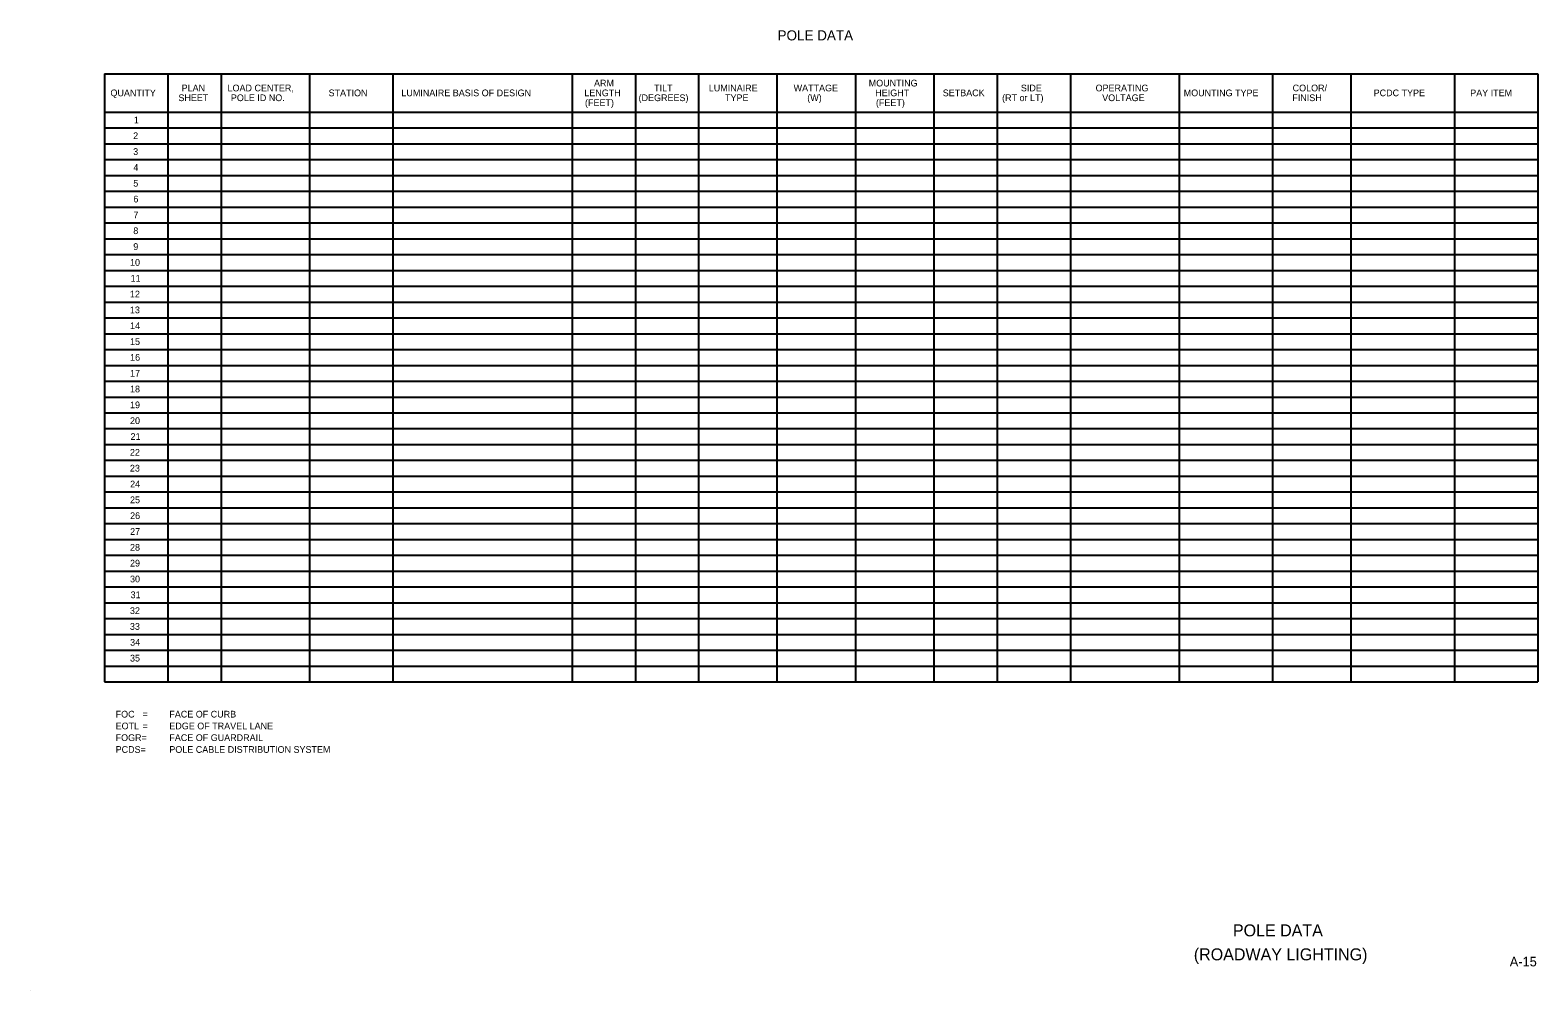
# Model space of a CAD drawing. Extents: x -830028.7 to -830013, y 1290283.4 to 1290293.4.
import ezdxf

# ---------------------------------------------------------------- set-up
doc = ezdxf.new("R2010")
doc.units = 0
for name, color, linetype in [('AdhocPoint_dp', 7, 'Continuous'), ('SumBoxBorder_dp', 7, 'Continuous'), ('SumBoxLines_dp', 7, 'Continuous'), ('SumBoxLinesMin_dp', 7, 'Continuous'), ('TextLabel', 7, 'Continuous'), ('TextMisc', 7, 'Continuous'), ('TextShtNo', 7, 'Continuous')]:
    doc.layers.add(name, color=color, linetype=linetype)

msp = doc.modelspace()

# ---------------------------------------------------------------- linework, layer by layer
at = {"layer": 'AdhocPoint_dp'}
msp.add_line((-830028.694, 1290283.415), (-830028.694, 1290283.415), dxfattribs=at)
at = {"layer": 'SumBoxBorder_dp'}
for p, q in [((-830027.917, 1290292.975), (-830012.97, 1290292.975)), ((-830027.917, 1290292.975), (-830012.97, 1290292.975)), ((-830027.917, 1290292.975), (-830027.917, 1290286.635)), ((-830016.712, 1290292.975), (-830016.712, 1290292.575)), ((-830015.737, 1290292.975), (-830015.737, 1290292.575)), ((-830014.92, 1290292.975), (-830014.92, 1290292.575)), ((-830013.84, 1290292.975), (-830013.84, 1290292.575)), ((-830012.97, 1290292.975), (-830012.97, 1290286.635)), ((-830027.917, 1290292.575), (-830012.97, 1290292.575)), ((-830027.917, 1290292.575), (-830012.97, 1290292.575)), ((-830027.917, 1290286.635), (-830012.97, 1290286.635))]:
    msp.add_line(p, q, dxfattribs=at)
at = {"layer": 'SumBoxLines_dp'}
for p, q in [((-830027.257, 1290292.975), (-830027.257, 1290286.635)), ((-830027.257, 1290292.975), (-830027.257, 1290286.635)), ((-830026.702, 1290292.975), (-830026.702, 1290286.635)), ((-830026.702, 1290292.975), (-830026.702, 1290286.635)), ((-830025.78, 1290292.975), (-830025.78, 1290286.635)), ((-830025.78, 1290292.975), (-830025.78, 1290286.635)), ((-830024.91, 1290292.975), (-830024.91, 1290286.635)), ((-830024.91, 1290292.975), (-830024.91, 1290286.635)), ((-830023.042, 1290292.975), (-830023.042, 1290286.635)), ((-830023.042, 1290292.975), (-830023.042, 1290286.635)), ((-830022.382, 1290292.975), (-830022.382, 1290286.635)), ((-830022.382, 1290292.975), (-830022.382, 1290286.635)), ((-830021.722, 1290292.975), (-830021.722, 1290286.635)), ((-830021.722, 1290292.975), (-830021.722, 1290286.635)), ((-830020.905, 1290292.975), (-830020.905, 1290286.635)), ((-830020.905, 1290292.975), (-830020.905, 1290286.635)), ((-830020.087, 1290292.975), (-830020.087, 1290286.635)), ((-830020.087, 1290292.975), (-830020.087, 1290286.635)), ((-830019.27, 1290292.975), (-830019.27, 1290286.635)), ((-830019.27, 1290292.975), (-830019.27, 1290286.635)), ((-830018.61, 1290292.975), (-830018.61, 1290286.635)), ((-830018.61, 1290292.975), (-830018.61, 1290286.635)), ((-830017.845, 1290292.975), (-830017.845, 1290286.635)), ((-830016.712, 1290292.975), (-830016.712, 1290286.635)), ((-830015.737, 1290292.975), (-830015.737, 1290286.635)), ((-830014.92, 1290292.975), (-830014.92, 1290286.635)), ((-830013.84, 1290292.975), (-830013.84, 1290286.635))]:
    msp.add_line(p, q, dxfattribs=at)
at = {"layer": 'SumBoxLinesMin_dp'}
for p, q in [((-830027.917, 1290292.41), (-830012.97, 1290292.41)), ((-830027.917, 1290292.41), (-830012.97, 1290292.41)), ((-830027.917, 1290292.245), (-830012.97, 1290292.245)), ((-830027.917, 1290292.245), (-830012.97, 1290292.245)), ((-830027.917, 1290292.08), (-830012.97, 1290292.08)), ((-830027.917, 1290292.08), (-830012.97, 1290292.08)), ((-830027.917, 1290291.915), (-830012.97, 1290291.915)), ((-830027.917, 1290291.915), (-830012.97, 1290291.915)), ((-830027.917, 1290291.75), (-830012.97, 1290291.75)), ((-830027.917, 1290291.75), (-830012.97, 1290291.75)), ((-830027.917, 1290291.585), (-830012.97, 1290291.585)), ((-830027.917, 1290291.585), (-830012.97, 1290291.585)), ((-830027.917, 1290291.42), (-830012.97, 1290291.42)), ((-830027.917, 1290291.42), (-830012.97, 1290291.42)), ((-830027.917, 1290291.255), (-830012.97, 1290291.255)), ((-830027.917, 1290291.255), (-830012.97, 1290291.255)), ((-830027.917, 1290291.09), (-830012.97, 1290291.09)), ((-830027.917, 1290291.09), (-830012.97, 1290291.09)), ((-830027.917, 1290290.925), (-830012.97, 1290290.925)), ((-830027.917, 1290290.925), (-830012.97, 1290290.925)), ((-830027.917, 1290290.76), (-830012.97, 1290290.76)), ((-830027.917, 1290290.76), (-830012.97, 1290290.76)), ((-830027.917, 1290290.595), (-830012.97, 1290290.595)), ((-830027.917, 1290290.595), (-830012.97, 1290290.595)), ((-830027.917, 1290290.43), (-830012.97, 1290290.43)), ((-830027.917, 1290290.43), (-830012.97, 1290290.43)), ((-830027.917, 1290290.265), (-830012.97, 1290290.265)), ((-830027.917, 1290290.265), (-830012.97, 1290290.265)), ((-830027.917, 1290290.1), (-830012.97, 1290290.1)), ((-830027.917, 1290290.1), (-830012.97, 1290290.1)), ((-830027.917, 1290289.935), (-830012.97, 1290289.935)), ((-830027.917, 1290289.935), (-830012.97, 1290289.935)), ((-830027.917, 1290289.77), (-830012.97, 1290289.77)), ((-830027.917, 1290289.77), (-830012.97, 1290289.77)), ((-830027.917, 1290289.605), (-830012.97, 1290289.605)), ((-830027.917, 1290289.605), (-830012.97, 1290289.605)), ((-830027.917, 1290289.44), (-830012.97, 1290289.44)), ((-830027.917, 1290289.44), (-830012.97, 1290289.44)), ((-830027.917, 1290289.275), (-830012.97, 1290289.275)), ((-830027.917, 1290289.275), (-830012.97, 1290289.275)), ((-830027.917, 1290289.11), (-830012.97, 1290289.11)), ((-830027.917, 1290289.11), (-830012.97, 1290289.11)), ((-830027.917, 1290288.945), (-830012.97, 1290288.945)), ((-830027.917, 1290288.945), (-830012.97, 1290288.945)), ((-830027.917, 1290288.78), (-830012.97, 1290288.78)), ((-830027.917, 1290288.78), (-830012.97, 1290288.78)), ((-830027.917, 1290288.615), (-830012.97, 1290288.615)), ((-830027.917, 1290288.615), (-830012.97, 1290288.615)), ((-830027.917, 1290288.45), (-830012.97, 1290288.45)), ((-830027.917, 1290288.45), (-830012.97, 1290288.45)), ((-830027.917, 1290288.285), (-830012.97, 1290288.285)), ((-830027.917, 1290288.285), (-830012.97, 1290288.285)), ((-830027.917, 1290288.12), (-830012.97, 1290288.12)), ((-830027.917, 1290288.12), (-830012.97, 1290288.12)), ((-830027.917, 1290287.955), (-830012.97, 1290287.955)), ((-830027.917, 1290287.955), (-830012.97, 1290287.955)), ((-830027.917, 1290287.79), (-830012.97, 1290287.79)), ((-830027.917, 1290287.79), (-830012.97, 1290287.79)), ((-830027.917, 1290287.625), (-830012.97, 1290287.625)), ((-830027.917, 1290287.625), (-830012.97, 1290287.625)), ((-830027.917, 1290287.46), (-830012.97, 1290287.46)), ((-830027.917, 1290287.46), (-830012.97, 1290287.46)), ((-830027.917, 1290287.295), (-830012.97, 1290287.295)), ((-830027.917, 1290287.295), (-830012.97, 1290287.295)), ((-830027.917, 1290287.13), (-830012.97, 1290287.13)), ((-830027.917, 1290287.13), (-830012.97, 1290287.13)), ((-830027.917, 1290286.965), (-830012.97, 1290286.965)), ((-830027.917, 1290286.965), (-830012.97, 1290286.965)), ((-830027.917, 1290286.8), (-830012.97, 1290286.8)), ((-830027.917, 1290286.8), (-830012.97, 1290286.8))]:
    msp.add_line(p, q, dxfattribs=at)

# ---------------------------------------------------------------- texts
at = {"layer": 'TextLabel'}
for s, height, p in [('POLE DATA', 0.105, (-830020.899, 1290293.322)), ('QUANTITY', 0.07, (-830027.856, 1290292.74)), ('PLAN', 0.07, (-830027.114, 1290292.791)), ('LOAD CENTER,', 0.07, (-830026.635, 1290292.791)), ('STATION', 0.07, (-830025.581, 1290292.74)), ('LUMINAIRE BASIS OF DESIGN', 0.07, (-830024.822, 1290292.74)), ('LENGTH', 0.07, (-830022.914, 1290292.74)), ('ARM', 0.07, (-830022.813, 1290292.842)), ('TILT', 0.07, (-830022.186, 1290292.791)), ('LUMINAIRE', 0.07, (-830021.616, 1290292.791)), ('WATTAGE', 0.07, (-830020.731, 1290292.791)), ('MOUNTING', 0.07, (-830019.948, 1290292.842)), ('HEIGHT', 0.07, (-830019.88, 1290292.74)), ('SETBACK', 0.07, (-830019.176, 1290292.74)), ('SIDE', 0.07, (-830018.361, 1290292.791)), ('OPERATING', 0.07, (-830017.582, 1290292.791)), ('MOUNTING TYPE', 0.07, (-830016.663, 1290292.74)), ('COLOR/', 0.07, (-830015.527, 1290292.791)), ('PCDC TYPE', 0.07, (-830014.682, 1290292.74)), ('PAY ITEM', 0.07, (-830013.675, 1290292.74)), ('SHEET', 0.07, (-830027.147, 1290292.689)), ('POLE ID NO.', 0.07, (-830026.6, 1290292.689)), ('(FEET)', 0.07, (-830022.907, 1290292.638)), ('(DEGREES)', 0.07, (-830022.348, 1290292.689)), ('TYPE', 0.07, (-830021.447, 1290292.689)), ('(W)', 0.07, (-830020.589, 1290292.689)), ('(FEET)', 0.07, (-830019.873, 1290292.638)), ('(RT or LT)', 0.07, (-830018.557, 1290292.689)), ('VOLTAGE', 0.07, (-830017.513, 1290292.689)), ('FINISH', 0.07, (-830015.53, 1290292.689)), ('1', 0.07, (-830027.612, 1290292.458)), ('2', 0.07, (-830027.619, 1290292.293)), ('3', 0.07, (-830027.619, 1290292.128)), ('4', 0.07, (-830027.617, 1290291.963)), ('5', 0.07, (-830027.618, 1290291.798)), ('6', 0.07, (-830027.617, 1290291.633)), ('7', 0.07, (-830027.617, 1290291.468)), ('8', 0.07, (-830027.618, 1290291.303)), ('9', 0.07, (-830027.618, 1290291.138)), ('10', 0.07, (-830027.652, 1290290.973)), ('11', 0.07, (-830027.646, 1290290.808)), ('12', 0.07, (-830027.653, 1290290.643)), ('13', 0.07, (-830027.653, 1290290.478)), ('14', 0.07, (-830027.651, 1290290.313)), ('15', 0.07, (-830027.652, 1290290.148)), ('16', 0.07, (-830027.651, 1290289.983)), ('17', 0.07, (-830027.651, 1290289.818)), ('18', 0.07, (-830027.652, 1290289.653)), ('19', 0.07, (-830027.652, 1290289.488)), ('20', 0.07, (-830027.652, 1290289.323)), ('21', 0.07, (-830027.646, 1290289.158)), ('22', 0.07, (-830027.653, 1290288.993)), ('23', 0.07, (-830027.653, 1290288.828)), ('24', 0.07, (-830027.651, 1290288.663)), ('25', 0.07, (-830027.652, 1290288.498)), ('26', 0.07, (-830027.651, 1290288.333)), ('27', 0.07, (-830027.651, 1290288.168)), ('28', 0.07, (-830027.652, 1290288.003)), ('29', 0.07, (-830027.652, 1290287.838)), ('30', 0.07, (-830027.652, 1290287.673)), ('31', 0.07, (-830027.646, 1290287.508)), ('32', 0.07, (-830027.653, 1290287.343)), ('33', 0.07, (-830027.653, 1290287.178)), ('34', 0.07, (-830027.651, 1290287.013)), ('35', 0.07, (-830027.652, 1290286.848)), ('FOC', 0.07, (-830027.802, 1290286.264)), ('EOTL', 0.07, (-830027.802, 1290286.141)), ('=', 0.07, (-830027.522, 1290286.264)), ('FACE OF CURB', 0.07, (-830027.242, 1290286.264)), ('EDGE OF TRAVEL LANE', 0.07, (-830027.242, 1290286.141)), ('FOGR=', 0.07, (-830027.802, 1290286.019)), ('=', 0.07, (-830027.522, 1290286.141)), ('FACE OF GUARDRAIL', 0.07, (-830027.242, 1290286.019)), ('PCDS=', 0.07, (-830027.802, 1290285.896)), ('POLE CABLE DISTRIBUTION SYSTEM', 0.07, (-830027.242, 1290285.896))]:
    msp.add_text(s, height=height, dxfattribs=at).set_placement(p)
at = {"layer": 'TextMisc'}
for s, p in [('       POLE DATA       ', (-830016.475, 1290283.983)), ('   (ROADWAY LIGHTING)   ', (-830016.697, 1290283.733))]:
    msp.add_text(s, height=0.125, dxfattribs=at).set_placement(p)
at = {"layer": 'TextShtNo'}
msp.add_text('A-15', height=0.1, dxfattribs=at).set_placement((-830013.263, 1290283.67))

doc.saveas('drawing.dxf')
